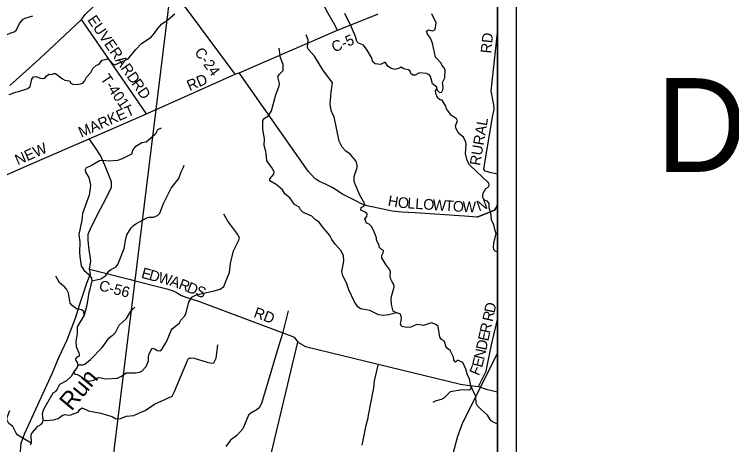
# Model space of a CAD drawing. Extents: x 0 to 34, y 0 to 22.
# Drawn here: x 6.32 to 10.15, y 18.045 to 20.34 of the extents above; entities that cross this region are included whole.
import ezdxf

# ---------------------------------------------------------------- set-up
doc = ezdxf.new("R2010")
doc.units = 0
for name, color, linetype in [('Default', 7, 'Continuous'), ('GM_X_County_Road', 7, 'Continuous'), ('GM_X_County_Road_Text', 7, 'Continuous'), ('GM_X_Minor_River', 7, 'Continuous'), ('GM_X_Minor_River_Text', 7, 'Continuous'), ('GM_X_Rail_Line', 7, 'Continuous'), ('GM_X_State_Route', 7, 'Continuous'), ('GM_X_Township_Road', 7, 'Continuous'), ('GM_X_Township_Road_Text', 7, 'Continuous'), ('SH_Cut_Line', 7, 'Continuous'), ('SH_Data', 7, 'Continuous'), ('SH_Text', 7, 'Continuous')]:
    doc.layers.add(name, color=color, linetype=linetype)

msp = doc.modelspace()

# ---------------------------------------------------------------- linework, layer by layer
at = {"layer": 'Default'}
msp.add_lwpolyline([(6.7802, 17.4233), (6.9652, 18.9204), (7.0779, 19.8324), (7.1423, 20.3535), (7.155, 20.4756), (7.1718, 20.7748), (7.1725, 20.7885), (6.8666, 20.8494), (6.6419, 20.8941), (2.4006, 20.8941), (2.3791, 20.1601), (2.3212, 18.6531), (2.2797, 17.8302)], dxfattribs=at)
at = {"layer": 'GM_X_County_Road'}
msp.add_line((7.4994, 20.0203), (7.5213, 20.0286), dxfattribs=at)
for points in [[(7.3101, 20.275), (7.2529, 20.3524), (7.2367, 20.3746), (7.186, 20.4403), (7.1552, 20.475), (7.1245, 20.5198), (7.022, 20.6419)], [(7.5213, 20.0286), (8.0456, 20.2555), (8.2553, 20.3401), (8.2608, 20.3425)], [(7.4994, 20.0203), (7.3136, 20.2702), (7.3101, 20.275)], [(7.0373, 19.8148), (7.0781, 19.8319), (7.4994, 20.0203)], [(8.7911, 19.2581), (8.7237, 19.2646), (8.4607, 19.2809), (8.3893, 19.2848), (8.3382, 19.2912), (8.263, 19.3059), (8.2048, 19.3189), (8.1732, 19.3301), (8.1395, 19.3482), (8.0727, 19.3808), (8.0201, 19.4146), (7.9811, 19.4351), (7.9458, 19.4502), (7.9238, 19.4649), (7.8899, 19.5038), (7.5213, 20.0286)], [(5.5935, 19.2775), (5.7264, 19.2583), (5.7427, 19.2576), (5.7571, 19.2562), (5.7629, 19.2588), (5.7962, 19.2737), (5.8137, 19.2814), (6.4281, 19.5499), (6.7192, 19.6766), (7.0264, 19.8102), (7.0346, 19.8137), (7.0373, 19.8148)], [(6.3508, 17.9888), (6.3563, 18.0541), (6.3759, 18.1068), (6.5246, 18.4278), (6.5579, 18.5101), (6.6026, 18.6045), (6.649, 18.7247), (6.6682, 18.7888), (6.7096, 18.9113), (6.7268, 18.9556), (6.7217, 18.9815), (6.7285, 19.0251), (6.7177, 19.098), (6.7148, 19.1368), (6.7149, 19.1679), (6.7317, 19.2081), (6.781, 19.3025), (6.807, 19.3529), (6.8292, 19.398), (6.8384, 19.4166), (6.8396, 19.4466), (6.803, 19.5363), (6.7811, 19.5873), (6.7542, 19.6287), (6.7192, 19.6766)], [(8.9, 19.3267), (8.8954, 19.3115), (8.8833, 19.2951), (8.7911, 19.2581)], [(6.7217, 18.9815), (6.9342, 18.9279), (6.9654, 18.9198), (7.0924, 18.8869)], [(7.0924, 18.8869), (7.135, 18.8759), (7.1629, 18.8675), (7.176, 18.8629), (7.1846, 18.8577), (7.1951, 18.8506), (7.2123, 18.8414), (7.2367, 18.8315), (7.3042, 18.8106), (7.8019, 18.6247), (7.815, 18.619), (7.8343, 18.5916), (7.8756, 18.5691), (8.7017, 18.367), (8.7498, 18.3599), (8.7979, 18.3561), (8.8392, 18.3414), (8.9, 18.3267)], [(7.5979, 17.6627), (7.5987, 17.6632), (7.6099, 17.6725), (7.6201, 17.697), (7.8343, 18.5916)]]:
    msp.add_lwpolyline(points, dxfattribs=at)
at = {"layer": 'GM_X_Minor_River'}
for points in [[(6.2932, 19.9132), (6.3279, 19.9251), (6.342, 19.929), (6.3931, 19.9452), (6.4047, 19.9553), (6.414, 19.9942), (6.4226, 20.0069), (6.4355, 20.0078), (6.4593, 19.9995), (6.4729, 19.9981), (6.4824, 20.0006), (6.4921, 20.0129), (6.5067, 20.0203), (6.5192, 20.0189), (6.5314, 20.0244), (6.5409, 20.025), (6.5779, 19.9955), (6.5907, 19.9885), (6.6145, 19.985), (6.6227, 19.9735), (6.6366, 19.9661), (6.662, 19.9683), (6.6731, 19.97), (6.6868, 19.9739), (6.6957, 19.984), (6.7055, 20.0055), (6.7291, 20.0297), (6.7393, 20.0512), (6.7597, 20.069), (6.7708, 20.0726), (6.7894, 20.0951), (6.7993, 20.0983), (6.8126, 20.1015), (6.8221, 20.1025), (6.8429, 20.0771), (6.8572, 20.0704), (6.9287, 20.1033), (6.9698, 20.153), (6.9999, 20.1852), (7.0506, 20.2192), (7.0692, 20.2397), (7.0844, 20.2634), (7.1083, 20.2888), (7.1275, 20.3017), (7.1409, 20.3117), (7.1771, 20.3426)], [(8.7309, 19.6577), (8.7179, 19.6845), (8.6939, 19.7045), (8.679, 19.7302), (8.6751, 19.745), (8.6857, 19.7729), (8.6813, 19.7833), (8.6542, 19.8011), (8.6274, 19.8356), (8.6238, 19.8508), (8.6038, 19.883), (8.5939, 19.885), (8.5819, 19.8924), (8.5701, 19.9176), (8.5691, 19.9313), (8.5765, 19.943), (8.5763, 19.9524), (8.5537, 19.9695), (8.5458, 19.9954), (8.5414, 20.0083), (8.5347, 20.0179), (8.5204, 20.0253), (8.4832, 20.0285), (8.4603, 20.0163), (8.4481, 20.0153), (8.438, 20.0242), (8.4336, 20.0375), (8.4239, 20.0438), (8.3985, 20.049), (8.3857, 20.058), (8.3762, 20.0524), (8.3514, 20.0463), (8.3283, 20.0527), (8.3148, 20.0635), (8.3, 20.0853), (8.2755, 20.0732), (8.2463, 20.0762), (8.2336, 20.0867), (8.2263, 20.1107), (8.2044, 20.1485), (8.1836, 20.1765), (8.1583, 20.186), (8.1486, 20.1956), (8.141, 20.2215), (8.1145, 20.2841), (8.1086, 20.296), (8.0839, 20.3449)], [(8.5765, 19.943), (8.5779, 19.9365), (8.5877, 19.925), (8.6002, 19.9236), (8.6072, 19.938), (8.6089, 19.9505), (8.6058, 19.9767), (8.6183, 20.0008), (8.6212, 20.0444), (8.6142, 20.0566), (8.6022, 20.0682), (8.5997, 20.0792), (8.5694, 20.1115), (8.5526, 20.1869), (8.5427, 20.2128), (8.5267, 20.2351), (8.5216, 20.2495), (8.5312, 20.2581), (8.5551, 20.2525), (8.5673, 20.2584), (8.572, 20.2955), (8.5487, 20.3433)], [(6.1628, 20.2891), (6.1843, 20.2406), (6.1985, 20.2278), (6.2242, 20.2221), (6.2732, 20.2284), (6.3069, 20.2438), (6.3198, 20.2474), (6.3317, 20.2574), (6.3479, 20.2909), (6.3669, 20.3137), (6.3783, 20.3199), (6.4184, 20.3318)], [(8.3609, 18.7485), (8.3436, 18.7567), (8.3331, 18.7933), (8.332, 18.8279), (8.3476, 18.8861), (8.3456, 18.8997), (8.3382, 18.9135), (8.33, 18.9284), (8.3276, 18.9436), (8.3287, 18.9668), (8.325, 18.9782), (8.3034, 19.0066), (8.2823, 19.041), (8.2828, 19.0532), (8.2899, 19.0679), (8.2908, 19.0807), (8.2784, 19.0877), (8.2679, 19.0989), (8.2677, 19.1091), (8.2536, 19.1351), (8.2538, 19.148), (8.2381, 19.1896), (8.2269, 19.2091), (8.2146, 19.2203), (8.2006, 19.2262), (8.1911, 19.2498), (8.203, 19.2626), (8.2032, 19.2759), (8.1927, 19.2847), (8.1697, 19.2957), (8.1718, 19.3097), (8.1856, 19.3167), (8.1911, 19.3295), (8.1651, 19.3754), (8.1394, 19.4338), (8.1339, 19.4495), (8.1339, 19.4749), (8.1509, 19.5225), (8.151, 19.5342), (8.1478, 19.5498), (8.1438, 19.5594), (8.1139, 19.5939), (8.0902, 19.6098), (8.0697, 19.631), (8.0542, 19.6638), (8.0272, 19.7928), (8.0205, 19.8051), (8.0113, 19.8272), (8.0072, 19.8618), (8.0112, 19.9251), (8.0183, 19.9751), (7.9673, 20.0434), (7.9235, 20.1164), (7.8895, 20.1541), (7.8863, 20.1644), (7.8895, 20.2034), (7.8788, 20.2301)], [(8.7148, 18.4832), (8.6868, 18.4962), (8.6764, 18.485), (8.6667, 18.4976), (8.6646, 18.5113), (8.6473, 18.548), (8.633, 18.5573), (8.6237, 18.568), (8.6198, 18.5874), (8.6142, 18.5989), (8.6003, 18.6063), (8.5925, 18.6186), (8.5823, 18.6752), (8.571, 18.6868), (8.5476, 18.6951), (8.5046, 18.6816), (8.4731, 18.6855), (8.4598, 18.6834), (8.4369, 18.6723), (8.4156, 18.6707), (8.3895, 18.676), (8.3821, 18.6872), (8.3867, 18.7193), (8.3857, 18.7311), (8.3802, 18.7422), (8.3609, 18.7485), (8.3186, 18.7374), (8.2924, 18.7347), (8.2651, 18.7385), (8.2184, 18.76), (8.1794, 18.7682), (8.168, 18.7691), (8.1541, 18.7807), (8.1367, 18.8071), (8.1068, 18.8709), (8.0933, 18.9075), (8.0741, 18.9449), (8.0687, 18.967), (8.0794, 19.0253), (8.0771, 19.0519), (8.0657, 19.079), (8.0324, 19.1144), (8.0161, 19.1392), (8.0054, 19.161), (7.9662, 19.2067), (7.9483, 19.232), (7.928, 19.2448), (7.9085, 19.2633), (7.8716, 19.2805), (7.8599, 19.2856), (7.8479, 19.2979), (7.8409, 19.3117), (7.8164, 19.3253), (7.7907, 19.3617), (7.766, 19.3814), (7.7526, 19.404), (7.7177, 19.4322), (7.6835, 19.4528), (7.6836, 19.4634), (7.706, 19.4881), (7.7077, 19.501), (7.694, 19.5251), (7.6679, 19.5581), (7.665, 19.598), (7.6629, 19.6079), (7.6535, 19.6399), (7.6551, 19.6748), (7.6467, 19.7288), (7.6462, 19.7735), (7.6559, 19.7863), (7.6781, 19.7981), (7.694, 19.8264), (7.7165, 19.9103), (7.7346, 19.9586), (7.7367, 19.9711), (7.7277, 20.0061), (7.7351, 20.0204), (7.7547, 20.0407), (7.7548, 20.0729), (7.742, 20.108), (7.7374, 20.1327), (7.7361, 20.1464), (7.7344, 20.1589)], [(7.1037, 19.7334), (7.0842, 19.7242), (7.0717, 19.6985), (7.0237, 19.6582), (7.0005, 19.6544), (6.963, 19.6314), (6.9522, 19.6183), (6.9462, 19.5948), (6.8953, 19.5694), (6.8713, 19.5614), (6.8269, 19.5571), (6.7886, 19.561), (6.7753, 19.5582), (6.7312, 19.5315), (6.7046, 19.5224), (6.6979, 19.5103), (6.7008, 19.4993), (6.7186, 19.4702), (6.7264, 19.4291), (6.7254, 19.4128), (6.7196, 19.3753), (6.6848, 19.2783), (6.6801, 19.2419), (6.6639, 19.1652), (6.6698, 19.1264), (6.6675, 19.0699), (6.6702, 19.0482), (6.6779, 18.9996), (6.6908, 18.9758), (6.7178, 18.9531), (6.7327, 18.9324), (6.7337, 18.9195), (6.7212, 18.8681), (6.7184, 18.8571), (6.708, 18.7897), (6.6936, 18.7361), (6.6566, 18.6744), (6.6561, 18.6372), (6.6491, 18.5952), (6.6499, 18.5694), (6.6668, 18.5297), (6.6662, 18.5176), (6.6532, 18.5113), (6.6444, 18.5008), (6.6526, 18.4893), (6.6574, 18.4798), (6.6591, 18.4703), (6.6559, 18.4585), (6.6373, 18.433), (6.6245, 18.4082), (6.5984, 18.3865), (6.5613, 18.3666), (6.5495, 18.3406), (6.538, 18.3278), (6.525, 18.3201), (6.4752, 18.2324), (6.4684, 18.2094), (6.4725, 18.1778), (6.4708, 18.1653), (6.4596, 18.1503), (6.4482, 18.1433), (6.4382, 18.1362), (6.4151, 18.11), (6.4077, 18.0976), (6.4105, 18.0536), (6.405, 18.0419)], [(8.9, 19.0716), (8.8891, 19.0773), (8.8809, 19.0869), (8.8784, 19.098), (8.8796, 19.12), (8.8929, 19.1706), (8.8853, 19.1927), (8.8797, 19.2174), (8.8684, 19.2438), (8.8669, 19.2711), (8.8554, 19.3078), (8.8562, 19.332), (8.8466, 19.3439), (8.8334, 19.3479), (8.8225, 19.3584), (8.8213, 19.3724), (8.823, 19.3868), (8.8367, 19.4109), (8.8501, 19.419), (8.8556, 19.4288), (8.8531, 19.4394), (8.7501, 19.5378), (8.738, 19.5612), (8.7292, 19.5981), (8.7326, 19.6462), (8.7309, 19.6577)], [(6.7337, 18.9195), (6.7824, 18.9302), (6.8088, 18.948), (6.8243, 18.9702), (6.8362, 18.9802), (6.8637, 18.9931), (6.8726, 19.0055), (6.8837, 19.0334), (6.9065, 19.0919), (6.9132, 19.1343), (6.9215, 19.1638), (6.9445, 19.2018), (6.9556, 19.2142), (6.9687, 19.2231), (7.0268, 19.2553), (7.0398, 19.2589), (7.0637, 19.2593), (7.0839, 19.2666), (7.0962, 19.2793), (7.1174, 19.331), (7.1225, 19.3419), (7.1569, 19.4132), (7.199, 19.4642), (7.2101, 19.4997), (7.2238, 19.5253), (7.2266, 19.5359)], [(6.6373, 18.433), (6.6425, 18.4204), (6.6561, 18.4191), (6.6686, 18.4136), (6.7039, 18.3892), (6.7183, 18.3844), (6.7426, 18.3898), (6.7697, 18.4027), (6.7842, 18.4025), (6.8057, 18.3972), (6.8703, 18.3994), (6.8928, 18.4097), (6.917, 18.4283), (6.9671, 18.4279), (6.9887, 18.4318), (7.0017, 18.4369), (7.0248, 18.4613), (7.0374, 18.4918), (7.0358, 18.5112), (7.0386, 18.5256), (7.0565, 18.5594), (7.0698, 18.5558), (7.0826, 18.5469), (7.0962, 18.5452), (7.1058, 18.5515), (7.1322, 18.5933), (7.1569, 18.6532), (7.1654, 18.6656), (7.1903, 18.6835), (7.2015, 18.6955), (7.2093, 18.7086), (7.2293, 18.7311), (7.2356, 18.7424), (7.2524, 18.8055), (7.2672, 18.8326), (7.2909, 18.8437), (7.3156, 18.849), (7.3872, 18.8651), (7.4184, 18.8749), (7.4395, 18.8879), (7.4592, 18.9392), (7.4686, 18.963), (7.4735, 19.0114), (7.4904, 19.0795), (7.5177, 19.1315), (7.5221, 19.1462), (7.5136, 19.1664), (7.4596, 19.237), (7.4381, 19.2741)], [(6.6936, 18.7361), (6.6915, 18.755), (6.6788, 18.7636), (6.6523, 18.77), (6.6294, 18.7867), (6.6178, 18.8001), (6.6094, 18.8526), (6.598, 18.8751), (6.5879, 18.8874), (6.562, 18.9079), (6.5413, 18.9446)], [(6.6591, 18.4703), (6.6861, 18.4702), (6.6971, 18.4746), (6.7263, 18.4989), (6.7887, 18.5629), (6.8262, 18.6158), (6.8377, 18.6244), (6.8481, 18.6303), (6.8604, 18.6442), (6.8807, 18.6833), (6.9195, 18.7181), (6.9428, 18.7568), (6.964, 18.7785)], [(7.7815, 18.759), (7.7521, 18.6387), (7.7287, 18.564), (7.6694, 18.366), (7.6399, 18.2652), (7.6271, 18.2414), (7.6174, 18.2321), (7.5838, 18.2136), (7.5707, 18.202), (7.5409, 18.13), (7.5081, 18.0945), (7.4736, 18.0684), (7.4489, 18.0361)], [(6.4725, 18.1778), (6.4884, 18.1734), (6.5302, 18.1785), (6.5542, 18.185), (6.5753, 18.2014), (6.5894, 18.2061), (6.6114, 18.2028), (6.6243, 18.2041), (6.6346, 18.21), (6.6617, 18.2191), (6.6702, 18.2327), (6.6833, 18.2423), (6.7157, 18.2252), (6.7812, 18.2129), (6.8348, 18.1981), (6.8454, 18.1945), (6.8593, 18.1852), (6.8729, 18.1824), (6.8878, 18.1852), (6.9183, 18.198), (6.9586, 18.2005), (7.0052, 18.2214), (7.0185, 18.2273), (7.0691, 18.2615), (7.1627, 18.3045), (7.1759, 18.3279), (7.2446, 18.4934), (7.2505, 18.5055), (7.26, 18.508), (7.2809, 18.5073), (7.35, 18.4847), (7.3727, 18.4802), (7.386, 18.4808), (7.3974, 18.5068), (7.4029, 18.5473), (7.4046, 18.5621), (7.4067, 18.5769)], [(8.1776, 18.0417), (8.1984, 18.1495), (8.2089, 18.1888), (8.2113, 18.2032), (8.2392, 18.3485), (8.2423, 18.3852), (8.2621, 18.4684)], [(8.9, 18.1545), (8.8815, 18.1626), (8.8669, 18.1731), (8.8466, 18.2034), (8.8137, 18.2305), (8.7928, 18.2521), (8.7854, 18.2658), (8.7838, 18.3023), (8.7578, 18.3588), (8.7505, 18.3958), (8.7439, 18.4088), (8.7373, 18.4225), (8.7309, 18.4484), (8.7148, 18.4832)], [(8.7578, 18.3588), (8.7571, 18.3425), (8.7498, 18.3355), (8.7135, 18.3372)], [(8.7135, 18.3372), (8.6472, 18.3276), (8.6134, 18.2935), (8.5996, 18.2861), (8.5672, 18.2775), (8.5546, 18.2708)], [(6.4105, 18.0536), (6.339, 18.0956), (6.3304, 18.1063), (6.3119, 18.1414), (6.2913, 18.1584), (6.2809, 18.1802), (6.2834, 18.1953), (6.2964, 18.2274)]]:
    msp.add_lwpolyline(points, dxfattribs=at)
at = {"layer": 'GM_X_Rail_Line'}
msp.add_lwpolyline([(6.7762, 14.3109), (6.9297, 14.4507), (7.5373, 15.0047), (7.83, 15.2691), (7.9287, 15.3625), (7.9592, 15.3949), (8.0363, 15.4875), (8.1684, 15.6475), (8.1886, 15.6755), (8.2095, 15.7107), (8.2296, 15.7554), (8.4079, 16.5494), (8.4762, 16.897), (8.4969, 16.9945), (8.5214, 17.0999), (8.5608, 17.4879), (8.571, 17.5663), (8.6067, 17.7431), (8.6649, 18.0046), (8.6886, 18.0902), (8.7141, 18.1631), (8.8658, 18.463), (8.9, 18.5325)], dxfattribs=at)
at = {"layer": 'GM_X_State_Route'}
msp.add_lwpolyline([(6.2956, 19.9604), (6.4341, 20.0826), (6.4833, 20.1299), (6.5043, 20.1498), (6.6785, 20.3128), (6.6982, 20.3384), (6.8371, 20.4739), (6.8679, 20.505), (6.9295, 20.564)], dxfattribs=at)
at = {"layer": 'GM_X_Township_Road'}
for p, q in [((6.7983, 20.1398), (6.6785, 20.3128)), ((8.8722, 19.9802), (8.9, 20.242)), ((7.0264, 19.8102), (6.7983, 20.1398))]:
    msp.add_line(p, q, dxfattribs=at)
for points in [[(8.0227, 20.2987), (7.9947, 20.3485), (7.9434, 20.4455), (7.816, 20.6694), (7.7783, 20.7267), (7.6571, 20.8941)], [(8.0456, 20.2555), (8.0237, 20.297), (8.0227, 20.2987)], [(8.9, 19.4878), (8.8592, 19.4972), (8.8418, 19.5017), (8.8316, 19.5057), (8.8261, 19.5145), (8.8733, 19.7927), (8.8813, 19.8332), (8.8795, 19.8583), (8.8669, 19.9303), (8.8722, 19.9802)], [(8.7911, 19.2581), (8.8833, 19.2951), (8.8954, 19.3115), (8.9, 19.3267)], [(8.7979, 18.3561), (8.8385, 18.4374), (8.8686, 18.5781), (8.9, 18.7136)]]:
    msp.add_lwpolyline(points, dxfattribs=at)
at = {"layer": 'SH_Cut_Line'}
msp.add_lwpolyline([(8.9, 14.2922), (8.9, 20.8941), (2.4006, 20.8941), (2.3791, 20.1601), (2.3212, 18.6531), (2.2797, 17.8302)], dxfattribs=at)
at = {"layer": 'SH_Data'}
for p, q in [((9, 21), (9, 14)), ((8.9, 20.9), (8.9, 14.1))]:
    msp.add_line(p, q, dxfattribs=at)

# ---------------------------------------------------------------- texts
at = {"layer": 'GM_X_County_Road_Text'}
for s, height, rotation, p in [('C-5', 0.05682, 22.6554, (8.0278, 20.1365)), ('C-24', 0.05682, 306.2531, (7.2793, 20.1375)), ('RD', 0.05682, 22.8105, (7.2561, 19.9307)), ('MARKET', 0.05682, 23.5827, (6.6775, 19.6822)), ('NEW', 0.05682, 23.4745, (6.3384, 19.5348)), ('H', 0.0568, 350.1894, (8.3116, 19.3194)), ('O', 0.0568, 354.9639, (8.366, 19.3102)), ('L', 0.0568, 356.1768, (8.4171, 19.3057)), ('L', 0.0568, 356.2342, (8.4596, 19.3029)), ('O', 0.0568, 356.2343, (8.502, 19.3001)), ('W', 0.0568, 356.2339, (8.5519, 19.2968)), ('T', 0.0568, 356.2342, (8.6175, 19.2925)), ('O', 0.0568, 356.2343, (8.66, 19.2897)), ('W', 0.0568, 358.5606, (8.7124, 19.2863)), ('N', 0.0568, 19.6727, (8.8006, 19.2882)), ('E', 0.0568, 344.9877, (6.9945, 18.9359)), ('D', 0.0568, 344.9843, (7.0356, 18.9249)), ('W', 0.0568, 344.679, (7.0838, 18.912)), ('C-56', 0.05682, 345.4657, (6.7683, 18.8695)), ('A', 0.0568, 341.4913, (7.1465, 18.8948)), ('R', 0.0568, 338.4972, (7.1932, 18.8792)), ('D', 0.0568, 338.1573, (7.2365, 18.8621)), ('S', 0.0568, 338.8448, (7.2836, 18.8433)), ('RD', 0.05682, 339.8498, (7.5941, 18.7269))]:
    msp.add_text(s, height=height, rotation=rotation, dxfattribs=at).set_placement(p)
at = {"layer": 'GM_X_Minor_River_Text'}
msp.add_text('Run', height=0.09466, rotation=50.385, dxfattribs=at).set_placement((6.6251, 18.2208))
at = {"layer": 'GM_X_Township_Road_Text'}
for s, height, rotation, p in [('EUVERARD', 0.05682, 304.7747, (6.7082, 20.3102)), ('RD', 0.05682, 84.0934, (8.8659, 20.1299)), ('T-401', 0.05682, 304.7841, (6.7779, 19.9972)), ('RD', 0.05682, 304.7888, (6.9431, 19.9712)), ('RURAL', 0.05682, 80.4042, (8.8069, 19.5305)), ('D', 0.0568, 77.4712, (8.8834, 18.7437)), ('R', 0.0568, 77.471, (8.8733, 18.6981)), ('R', 0.0568, 77.4718, (8.8594, 18.6355)), ('E', 0.0568, 77.4733, (8.8502, 18.594)), ('D', 0.0568, 77.4725, (8.8393, 18.5452)), ('N', 0.0568, 77.4733, (8.8285, 18.4964)), ('E', 0.0568, 75.8802, (8.8177, 18.4535)), ('F', 0.0568, 67.352, (8.8001, 18.4095))]:
    msp.add_text(s, height=height, rotation=rotation, dxfattribs=at).set_placement(p)
at = {"layer": 'SH_Text'}
msp.add_text('DEPARTMENT OF TRANSPORTATION', height=0.5, dxfattribs=at).set_placement((9.7466, 19.5))

doc.saveas('drawing.dxf')
